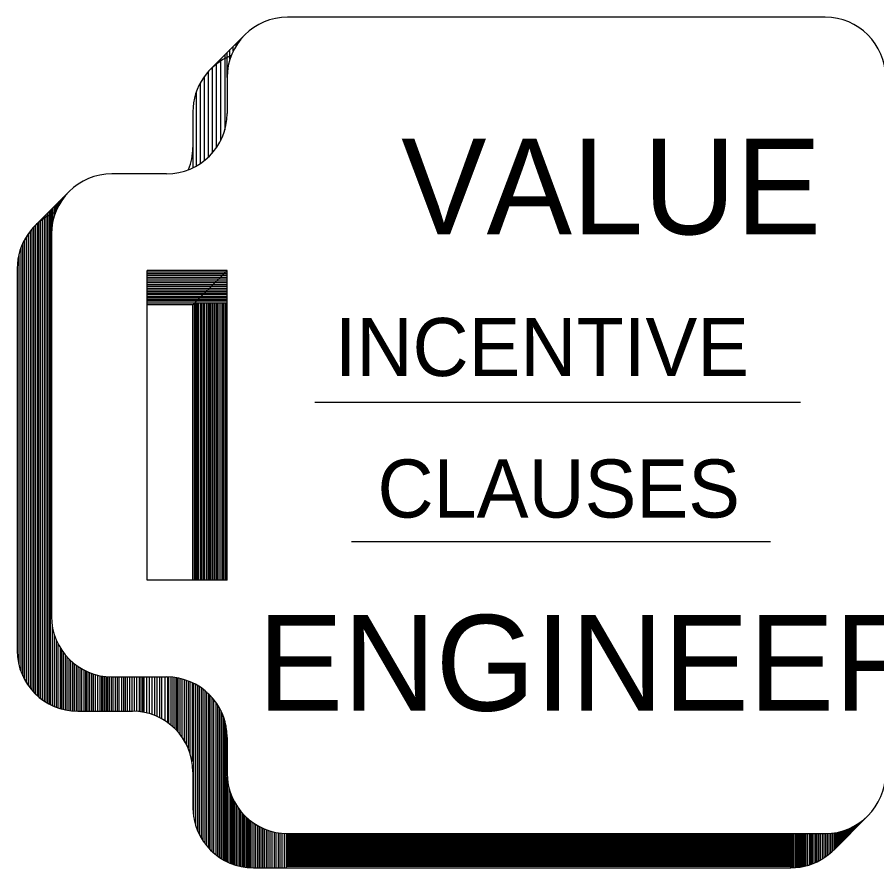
# Model space of a CAD drawing. Extents: x 0 to 53.3, y -0.3 to 37.1.
# Drawn here: x 3.297 to 4.481, y 1.819 to 2.992 of the extents above; entities that cross this region are included whole.
import ezdxf

# ---------------------------------------------------------------- set-up
doc = ezdxf.new("R2010")
doc.units = 0
doc.layers.add('Level 1', color=7, linetype='Continuous')

msp = doc.modelspace()

# ---------------------------------------------------------------- linework, layer by layer
at = {"layer": 'Level 1'}
for p, q in [((4.4099, 2.9916), (3.6692, 2.9916)), ((3.5631, 2.9201), (3.6102, 2.9673)), ((3.5942, 2.9446), (3.5942, 2.9513)), ((3.5984, 2.9521), (3.5984, 2.9554)), ((3.6019, 2.9574), (3.6019, 2.9589)), ((3.5826, 2.9396), (3.5826, 2.8358)), ((3.5859, 2.9083), (3.5859, 2.9429)), ((3.5899, 2.9338), (3.5899, 2.9469)), ((3.5709, 2.9279), (3.5709, 2.8114)), ((3.5769, 2.9339), (3.5769, 2.8214)), ((3.5597, 2.9164), (3.5597, 2.7984)), ((3.5652, 2.9223), (3.5652, 2.8041)), ((3.5541, 2.9093), (3.5541, 2.7936)), ((3.5859, 2.9083), (3.5859, 2.8591)), ((3.5489, 2.9009), (3.5489, 2.7898)), ((3.5432, 2.8881), (3.5432, 2.7864)), ((3.5387, 2.8611), (3.5387, 2.7841)), ((3.5026, 2.7758), (3.4272, 2.7758)), ((3.3211, 2.7043), (3.3682, 2.7514)), ((3.3531, 2.7304), (3.3531, 2.7363)), ((3.3547, 2.7336), (3.3547, 2.7379)), ((3.3564, 2.7363), (3.3564, 2.7396)), ((3.3581, 2.7389), (3.3581, 2.7413)), ((3.3597, 2.7413), (3.3597, 2.7429)), ((3.3421, 2.7253), (3.3421, 2.0444)), ((3.3439, 2.6924), (3.3439, 2.7271)), ((3.3457, 2.7098), (3.3457, 2.7289)), ((3.3481, 2.7184), (3.3481, 2.7313)), ((3.3499, 2.7234), (3.3499, 2.7331)), ((3.3516, 2.7273), (3.3516, 2.7348)), ((3.3311, 2.7143), (3.3311, 2.0513)), ((3.3339, 2.7171), (3.3339, 2.0493)), ((3.3362, 2.7194), (3.3362, 2.0478)), ((3.3384, 2.7216), (3.3384, 2.0464)), ((3.3406, 2.7238), (3.3406, 2.0453)), ((3.3191, 2.7021), (3.3191, 2.0618)), ((3.3214, 2.7044), (3.3214, 2.0594)), ((3.3242, 2.7074), (3.3242, 2.0568)), ((3.3262, 2.7094), (3.3262, 2.0549)), ((3.3284, 2.7116), (3.3284, 2.0533)), ((3.3091, 2.6889), (3.3091, 2.0749)), ((3.3117, 2.6929), (3.3117, 2.0709)), ((3.3146, 2.6968), (3.3146, 2.0671)), ((3.3169, 2.6996), (3.3169, 2.0643)), ((3.3439, 2.6924), (3.3439, 2.1658)), ((3.3042, 2.6798), (3.3042, 2.0841)), ((3.3064, 2.6843), (3.3064, 2.0796)), ((3.2991, 2.6648), (3.2991, 2.0991)), ((3.3016, 2.6733), (3.3016, 2.0906)), ((3.2967, 2.6453), (3.2967, 2.1186)), ((3.5859, 2.6424), (3.4756, 2.6424)), ((3.4756, 2.2158), (3.4756, 2.6424)), ((3.5859, 2.6424), (3.5387, 2.5953)), ((3.5859, 2.2158), (3.5859, 2.6424)), ((3.5859, 2.6403), (3.4756, 2.6403)), ((3.5859, 2.6381), (3.4756, 2.6381)), ((3.5859, 2.6356), (3.4756, 2.6356)), ((3.5859, 2.6331), (3.4756, 2.6331)), ((3.5859, 2.6304), (3.4756, 2.6304)), ((3.5859, 2.6279), (3.4756, 2.6279)), ((3.5859, 2.6254), (3.4756, 2.6254)), ((3.5859, 2.6228), (3.4756, 2.6228)), ((3.5859, 2.6204), (3.4756, 2.6204)), ((3.5859, 2.6179), (3.4756, 2.6179)), ((3.5859, 2.6154), (3.4756, 2.6154)), ((3.5859, 2.6131), (3.4756, 2.6131)), ((3.5859, 2.6108), (3.4756, 2.6108)), ((3.5859, 2.6088), (3.4756, 2.6088)), ((3.5859, 2.6063), (3.4756, 2.6063)), ((3.5859, 2.6043), (3.4756, 2.6043)), ((3.5859, 2.6021), (3.4756, 2.6021)), ((3.5859, 2.6001), (3.4756, 2.6001)), ((3.5859, 2.5976), (3.4756, 2.5976)), ((3.5387, 2.5953), (3.4756, 2.5953)), ((3.5387, 2.2158), (3.5387, 2.5953)), ((3.5411, 2.2158), (3.5411, 2.5976)), ((3.5429, 2.2158), (3.5429, 2.5976)), ((3.5449, 2.2158), (3.5449, 2.5976)), ((3.5466, 2.2158), (3.5466, 2.5976)), ((3.5491, 2.2158), (3.5491, 2.5976)), ((3.5512, 2.2158), (3.5512, 2.5976)), ((3.5536, 2.2158), (3.5536, 2.5976)), ((3.5552, 2.2158), (3.5552, 2.5976)), ((3.5579, 2.2158), (3.5579, 2.5976)), ((3.5601, 2.2158), (3.5601, 2.5976)), ((3.5619, 2.2158), (3.5619, 2.5976)), ((3.5641, 2.2158), (3.5641, 2.5976)), ((3.5662, 2.2158), (3.5662, 2.5976)), ((3.5687, 2.2158), (3.5687, 2.5976)), ((3.5707, 2.2158), (3.5707, 2.5976)), ((3.5727, 2.2158), (3.5727, 2.5976)), ((3.5752, 2.2158), (3.5752, 2.5976)), ((3.5777, 2.2158), (3.5777, 2.5976)), ((3.5802, 2.2158), (3.5802, 2.5976)), ((3.5819, 2.2158), (3.5819, 2.5976)), ((3.5841, 2.2158), (3.5841, 2.5976)), ((3.7067, 2.4613), (4.3759, 2.4613)), ((3.7571, 2.2693), (4.3346, 2.2693)), ((3.5859, 2.2158), (3.4756, 2.2158)), ((3.3451, 2.1519), (3.3451, 2.0429)), ((3.3477, 2.1408), (3.3477, 2.0418)), ((3.3502, 2.1339), (3.3502, 2.0408)), ((3.3527, 2.1284), (3.3527, 2.0399)), ((3.3557, 2.1229), (3.3557, 2.0389)), ((3.3579, 2.1196), (3.3579, 2.0383)), ((3.3601, 2.1164), (3.3601, 2.0378)), ((3.3629, 2.1128), (3.3629, 2.0371)), ((3.3652, 2.1101), (3.3652, 2.0366)), ((3.3677, 2.1074), (3.3677, 2.0363)), ((3.3702, 2.1049), (3.3702, 2.0358)), ((3.3727, 2.1028), (3.3727, 2.0356)), ((3.3751, 2.1008), (3.3751, 2.0354)), ((3.3779, 2.0986), (3.3779, 2.0353)), ((3.3804, 2.0968), (3.3804, 2.0353)), ((3.3829, 2.0953), (3.3829, 2.0353)), ((3.3854, 2.0938), (3.3854, 2.0353)), ((3.3884, 2.0921), (3.3884, 2.0353)), ((3.3906, 2.0909), (3.3906, 2.0353)), ((3.3919, 2.0903), (3.3919, 2.0353)), ((3.3941, 2.0893), (3.3941, 2.0353)), ((3.3962, 2.0884), (3.3962, 2.0353)), ((3.3989, 2.0874), (3.3989, 2.0353)), ((3.4016, 2.0864), (3.4016, 2.0353)), ((3.4041, 2.0858), (3.4041, 2.0353)), ((3.4074, 2.0848), (3.4074, 2.0353)), ((3.4104, 2.0841), (3.4104, 2.0353)), ((3.4129, 2.0836), (3.4129, 2.0353)), ((3.4147, 2.0834), (3.4147, 2.0353)), ((3.4172, 2.0831), (3.4172, 2.0353)), ((3.4194, 2.0828), (3.4194, 2.0353)), ((3.4212, 2.0826), (3.4212, 2.0353)), ((3.4236, 2.0824), (3.4236, 2.0353)), ((3.4262, 2.0824), (3.4262, 2.0353)), ((3.4272, 2.0824), (3.5026, 2.0824)), ((3.4287, 2.0824), (3.4287, 2.0353)), ((3.4316, 2.0824), (3.4316, 2.0353)), ((3.4344, 2.0824), (3.4344, 2.0353)), ((3.4369, 2.0824), (3.4369, 2.0353)), ((3.4402, 2.0824), (3.4402, 2.0353)), ((3.4431, 2.0824), (3.4431, 2.0353)), ((3.4456, 2.0824), (3.4456, 2.0353)), ((3.4484, 2.0824), (3.4484, 2.0353)), ((3.4516, 2.0824), (3.4516, 2.0353)), ((3.4546, 2.0824), (3.4546, 2.0353)), ((3.4577, 2.0824), (3.4577, 2.0353)), ((3.4609, 2.0824), (3.4609, 2.0353)), ((3.4646, 2.0824), (3.4646, 2.0348)), ((3.4671, 2.0824), (3.4671, 2.0344)), ((3.4692, 2.0824), (3.4692, 2.0341)), ((3.4714, 2.0824), (3.4714, 2.0338)), ((3.4749, 2.0824), (3.4749, 2.0329)), ((3.4786, 2.0824), (3.4786, 2.0319)), ((3.4824, 2.0824), (3.4824, 2.0308)), ((3.4861, 2.0824), (3.4861, 2.0294)), ((3.4892, 2.0824), (3.4892, 2.0281)), ((3.4929, 2.0824), (3.4929, 2.0264)), ((3.4957, 2.0824), (3.4957, 2.0249)), ((3.5001, 2.0824), (3.5001, 2.0223)), ((3.5036, 2.0824), (3.5036, 2.0199)), ((3.5054, 2.0824), (3.5054, 2.0186)), ((3.5086, 2.0824), (3.5086, 2.0161)), ((3.5111, 2.0819), (3.5111, 2.0139)), ((3.5137, 2.0816), (3.5137, 2.0114)), ((3.5162, 2.0813), (3.5162, 2.0089)), ((3.5181, 2.0809), (3.5181, 2.0069)), ((3.5209, 2.0804), (3.5209, 2.0034)), ((3.5237, 2.0798), (3.5237, 1.9996)), ((3.5267, 2.0789), (3.5267, 1.9949)), ((3.5296, 2.0779), (3.5296, 1.9899)), ((3.5321, 2.0771), (3.5321, 1.9846)), ((3.5347, 2.0759), (3.5347, 1.9774)), ((3.5376, 2.0748), (3.5376, 1.9658)), ((3.5397, 2.0738), (3.5397, 1.8899)), ((3.5424, 2.0723), (3.5424, 1.8783)), ((3.5451, 2.0708), (3.5451, 1.8709)), ((3.5476, 2.0693), (3.5476, 1.8654)), ((3.5501, 2.0676), (3.5501, 1.8608)), ((3.5526, 2.0658), (3.5526, 1.8568)), ((3.5554, 2.0636), (3.5554, 1.8528)), ((3.5576, 2.0618), (3.5576, 1.8499)), ((3.5601, 2.0594), (3.5601, 1.8471)), ((3.5622, 2.0573), (3.5622, 1.8448)), ((3.5649, 2.0544), (3.5649, 1.8421)), ((3.5674, 2.0514), (3.5674, 1.8399)), ((3.5702, 2.0478), (3.5702, 1.8374)), ((3.5729, 2.0438), (3.5729, 1.8354)), ((3.5751, 2.0403), (3.5751, 1.8339)), ((3.3801, 2.0353), (3.4554, 2.0353)), ((3.5771, 2.0364), (3.5771, 1.8326)), ((3.5787, 2.0329), (3.5787, 1.8316)), ((3.5809, 2.0276), (3.5809, 1.8303)), ((3.5827, 2.0219), (3.5827, 1.8293)), ((3.5842, 2.0156), (3.5842, 1.8284)), ((3.5859, 1.9991), (3.5859, 1.9499)), ((3.5387, 1.9519), (3.5387, 1.9028)), ((3.5861, 1.9446), (3.5861, 1.8276)), ((3.5884, 1.9296), (3.5884, 1.8266)), ((3.5906, 1.9224), (3.5906, 1.8256)), ((3.5924, 1.9176), (3.5924, 1.8249)), ((3.5944, 1.9133), (3.5944, 1.8241)), ((3.5961, 1.9101), (3.5961, 1.8236)), ((3.5984, 1.9061), (3.5984, 1.8229)), ((3.6006, 1.9028), (3.6006, 1.8223)), ((3.6029, 1.8994), (3.6029, 1.8216)), ((3.6046, 1.8974), (3.6046, 1.8213)), ((3.6069, 1.8946), (3.6069, 1.8208)), ((3.6082, 1.8931), (3.6082, 1.8206)), ((3.6101, 1.8913), (3.6101, 1.8203)), ((3.6121, 1.8893), (3.6121, 1.8201)), ((3.6136, 1.8879), (3.6136, 1.8199)), ((3.6146, 1.8871), (3.6146, 1.8198)), ((3.6157, 1.8861), (3.6157, 1.8196)), ((3.6176, 1.8846), (3.6176, 1.8196)), ((4.4217, 1.8438), (4.4689, 1.8909)), ((4.4599, 1.8819), (4.4599, 1.8833)), ((3.6199, 1.8828), (3.6199, 1.8196)), ((3.6226, 1.8809), (3.6226, 1.8196)), ((3.6249, 1.8794), (3.6249, 1.8196)), ((3.6276, 1.8778), (3.6276, 1.8196)), ((3.6301, 1.8764), (3.6301, 1.8196)), ((3.6326, 1.8751), (3.6326, 1.8196)), ((3.6346, 1.8741), (3.6346, 1.8196)), ((3.6369, 1.8731), (3.6369, 1.8196)), ((3.6396, 1.8721), (3.6396, 1.8196)), ((4.4379, 1.8599), (4.4379, 1.8714)), ((4.4396, 1.8616), (4.4396, 1.8721)), ((4.4406, 1.8626), (4.4406, 1.8724)), ((4.4426, 1.8646), (4.4426, 1.8733)), ((4.4441, 1.8661), (4.4441, 1.8739)), ((4.4457, 1.8678), (4.4457, 1.8748)), ((4.4476, 1.8696), (4.4476, 1.8756)), ((4.4491, 1.8711), (4.4491, 1.8764)), ((4.4506, 1.8726), (4.4506, 1.8773)), ((4.4521, 1.8741), (4.4521, 1.8781)), ((4.4537, 1.8758), (4.4537, 1.8791)), ((4.4554, 1.8774), (4.4554, 1.8801)), ((4.4569, 1.8789), (4.4569, 1.8811)), ((4.4584, 1.8804), (4.4584, 1.8821)), ((3.6422, 1.8711), (3.6422, 1.8196)), ((3.6449, 1.8703), (3.6449, 1.8196)), ((3.6477, 1.8694), (3.6477, 1.8196)), ((3.6507, 1.8686), (3.6507, 1.8196)), ((3.6531, 1.8681), (3.6531, 1.8196)), ((3.6561, 1.8676), (3.6561, 1.8196)), ((3.6587, 1.8673), (3.6587, 1.8196)), ((3.6614, 1.8669), (3.6614, 1.8196)), ((3.6646, 1.8668), (3.6646, 1.8196)), ((3.6672, 1.8666), (3.6672, 1.8196)), ((3.6672, 1.8654), (4.3627, 1.8654)), ((3.6672, 1.8646), (4.3627, 1.8646)), ((3.6672, 1.8638), (4.3627, 1.8638)), ((3.6672, 1.8626), (4.3627, 1.8626)), ((3.6672, 1.8613), (4.3627, 1.8613)), ((3.6672, 1.8598), (4.3627, 1.8598)), ((3.6692, 1.8666), (4.4099, 1.8666)), ((4.3627, 1.8194), (4.3627, 1.8666)), ((4.3646, 1.8194), (4.3646, 1.8666)), ((4.3659, 1.8194), (4.3659, 1.8666)), ((4.3672, 1.8196), (4.3672, 1.8666)), ((4.3694, 1.8198), (4.3694, 1.8666)), ((4.3711, 1.8199), (4.3711, 1.8666)), ((4.3731, 1.8201), (4.3731, 1.8666)), ((4.3747, 1.8203), (4.3747, 1.8666)), ((4.3766, 1.8206), (4.3766, 1.8666)), ((4.3781, 1.8209), (4.3781, 1.8666)), ((4.3801, 1.8213), (4.3801, 1.8666)), ((4.3819, 1.8216), (4.3819, 1.8666)), ((4.3837, 1.8221), (4.3837, 1.8666)), ((4.3861, 1.8228), (4.3861, 1.8666)), ((4.3886, 1.8236), (4.3886, 1.8666)), ((4.3906, 1.8243), (4.3906, 1.8666)), ((4.3926, 1.8249), (4.3926, 1.8666)), ((4.3947, 1.8258), (4.3947, 1.8666)), ((4.3969, 1.8268), (4.3969, 1.8666)), ((4.3987, 1.8276), (4.3987, 1.8666)), ((4.4012, 1.8289), (4.4012, 1.8666)), ((4.4037, 1.8303), (4.4037, 1.8666)), ((4.4061, 1.8316), (4.4061, 1.8666)), ((4.4084, 1.8331), (4.4084, 1.8666)), ((4.4107, 1.8346), (4.4107, 1.8666)), ((4.4129, 1.8363), (4.4129, 1.8666)), ((4.4152, 1.8381), (4.4152, 1.8666)), ((4.4177, 1.8401), (4.4177, 1.8669)), ((4.4201, 1.8423), (4.4201, 1.8673)), ((4.4221, 1.8441), (4.4221, 1.8674)), ((4.4242, 1.8463), (4.4242, 1.8678)), ((4.4259, 1.8479), (4.4259, 1.8681)), ((4.4279, 1.8499), (4.4279, 1.8686)), ((4.4296, 1.8516), (4.4296, 1.8689)), ((4.4314, 1.8534), (4.4314, 1.8694)), ((4.4334, 1.8554), (4.4334, 1.8699)), ((4.4347, 1.8568), (4.4347, 1.8704)), ((4.4364, 1.8584), (4.4364, 1.8709)), ((3.6672, 1.8583), (4.3627, 1.8583)), ((3.6672, 1.8569), (4.3627, 1.8569)), ((3.6672, 1.8554), (4.3627, 1.8554)), ((3.6672, 1.8539), (4.3627, 1.8539)), ((3.6672, 1.8524), (4.3627, 1.8524)), ((3.6672, 1.8509), (4.3627, 1.8509)), ((3.6672, 1.8494), (4.3627, 1.8494)), ((3.6672, 1.8481), (4.3627, 1.8481)), ((3.6672, 1.8466), (4.3627, 1.8466)), ((3.6672, 1.8453), (4.3627, 1.8453)), ((3.6672, 1.8439), (4.3627, 1.8439)), ((3.6672, 1.8424), (4.3627, 1.8424)), ((3.6672, 1.8409), (4.3627, 1.8409)), ((3.6672, 1.8393), (4.3627, 1.8393)), ((3.6672, 1.8376), (4.3627, 1.8376)), ((3.6672, 1.8359), (4.3627, 1.8359)), ((3.6672, 1.8344), (4.3627, 1.8344)), ((3.6672, 1.8326), (4.3627, 1.8326)), ((3.6672, 1.8309), (4.3627, 1.8309)), ((3.6672, 1.8291), (4.3627, 1.8291)), ((3.6672, 1.8273), (4.3627, 1.8273)), ((3.6672, 1.8253), (4.3627, 1.8253)), ((3.6221, 1.8194), (4.3627, 1.8194)), ((3.6672, 1.8234), (4.3627, 1.8234)), ((3.6672, 1.8216), (4.3627, 1.8216))]:
    msp.add_line(p, q, dxfattribs=at)
for centre, start, end in [((3.6692, 2.9083), 90, 180), ((4.4099, 2.9083), 0, 90), ((3.6221, 2.8611), 111.4079, 180), ((3.5026, 2.8591), 270, 0), ((3.4554, 2.8119), 338.5921, 0), ((3.4272, 2.6924), 90, 180), ((3.3801, 2.6453), 111.4079, 180), ((3.4272, 2.1658), 180, 270), ((3.3801, 2.1186), 180, 270), ((3.5026, 1.9991), 0, 90), ((3.4554, 1.9519), 0, 90), ((3.6692, 1.9499), 180, 270), ((4.4099, 1.9499), 270, 0), ((3.6221, 1.9028), 180, 270), ((4.3627, 1.9028), 270, 338.5921)]:
    msp.add_arc(centre, 0.0833, start, end, dxfattribs=at)

# ---------------------------------------------------------------- texts
for s, height, p in [('VALUE', 0.13199, (3.8257, 2.6924)), ('INCENTIVE', 0.08, (3.7344, 2.4971)), ('CLAUSES', 0.08, (3.7931, 2.3021)), ('ENGINEERING', 0.13199, (3.6281, 2.0359))]:
    msp.add_text(s, height=height, dxfattribs=at).set_placement(p)

doc.saveas('drawing.dxf')
